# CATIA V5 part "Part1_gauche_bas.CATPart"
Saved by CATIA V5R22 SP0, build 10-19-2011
Part number: Part1
Bounding box of the stored display mesh (mm): x -87.5 to 0, y -87.5 to 89.999, z 0 to 150
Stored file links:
  C:\Users\dussa\Documents\ENIB\S5\inter\Part1_gauche_bas.CATPart
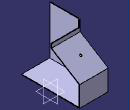
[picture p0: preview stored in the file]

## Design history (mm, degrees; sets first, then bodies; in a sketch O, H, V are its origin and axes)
Body1 (main body)
  Sketch1 on xy-plane, origin (0, 0, 0), H (1, 0, 0), V (0, 1, 0)
    line L1 (-87.5, 87.5) -> (87.5, 87.5)
    line L2 (87.5, 87.5) -> (87.5, -87.5)
    line L3 (87.5, -87.5) -> (-87.5, -87.5)
    line L4 (-87.5, -87.5) -> (-87.5, 87.5)
    distance L1 L3 = 175
    distance L4 L2 = 175
    horizontal: L1 H, L3 H
    vertical: L2 V, L4 V
    symmetry: L3 L1 H, L4 L2 V
  Pad1: profile Sketch1, direction (0, 0, 1), length 2
  Sketch2 on face of Pad1 from Sketch1.L2, origin (87.5, 0, 0), H (0, 1, 0), V (0, 0, 1)
    point P1 (-87.5, 0)
    line L1 (-87.5, 0) -> (87.5, 0)
    line L2 (87.5, 0) -> (87.5, 62.3217)
    line L3 (-87.5, 80) -> (-87.5, 0)
    point P3 (87.5, 62.3217)
    point P4 (-87.5, 80)
    reference projected line E1 (-87.5, 0) -> (-87.5, 2) from edge [face of Pad1 from Sketch1.L2 | face of Pad1 from Sketch1.L3]
    reference projected line E2 (87.5, 0) -> (87.5, 2) from edge [face of Pad1 from Sketch1.L1 | face of Pad1 from Sketch1.L2]
    reference projected line E3 (-87.5, 0) -> (87.5, 0) from edge [start face of Pad1 | face of Pad1 from Sketch1.L2]
    line L4 (-87.5, 300) -> (2.5, 300)
    line L5 (2.5, 300) -> (2.5, 115)
    line L6 (-87.5, 80) -> (-87.5, 300)
    point P8 (-87.5, 80)
    line L7 (2.5, 115) -> (87.5, 62.3217)
    point P9 (87.5, 62.3217)
    distance P4 P1 = 80
    distance L1 L4 = 300
    length L5 = 185
    distance L5 L6 = 90
    length L7 = 100
    horizontal: L1 H, L4 H
    vertical: L2 V, L3 V, L5 V, L6 V
    coincidence: E1 L3, L2 E2, L1 E3, L6 L3, P8 P4, L7 P3, P3 P9
  Pad2: profile Sketch2, direction (1, 0, 0), length 2
  Sketch3 on face of Pad1 from Sketch1.L4, origin (-87.5, 0, 0), H (0, 1, 0), V (0, 0, 1)
    point P1 (-87.5, 0)
    line L1 (-87.5, 0) -> (87.5, 0)
    line L2 (87.5, 0) -> (87.5, 62.3217)
    line L3 (-87.5, 80) -> (-87.5, 0)
    point P3 (87.5, 62.3217)
    point P4 (-87.5, 80)
    reference projected line E1 (-87.5, 0) -> (-87.5, 2) from edge [face of Pad1 from Sketch1.L2 | face of Pad1 from Sketch1.L3]
    reference projected line E2 (87.5, 0) -> (87.5, 2) from edge [face of Pad1 from Sketch1.L1 | face of Pad1 from Sketch1.L2]
    reference projected line E3 (-87.5, 0) -> (87.5, 0) from edge [start face of Pad1 | face of Pad1 from Sketch1.L2]
    line L4 (-87.5, 300) -> (2.5, 300)
    line L5 (2.5, 300) -> (2.5, 115)
    line L6 (-87.5, 80) -> (-87.5, 300)
    point P8 (-87.5, 80)
    line L7 (2.5, 115) -> (87.5, 62.3217)
    point P9 (87.5, 62.3217)
    distance P4 P1 = 80
    distance L1 L4 = 300
    length L5 = 185
    distance L5 L6 = 90
    length L7 = 100
    horizontal: L1 H, L4 H
    vertical: L2 V, L3 V, L5 V, L6 V
    coincidence: E1 L3, L2 E2, L1 E3, L6 L3, P8 P4, L7 P3, P3 P9
  Pad3: profile Sketch3, direction (1, 0, 0), length 2
  Sketch4 on face of Pad3 from Sketch3.L4, origin (0, 0, 300), H (1, 0, 0), V (0, 1, 0)
    line L1 (-87.5, 2.5) -> (89.5, 2.5)
    line L2 (89.5, 2.5) -> (89.5, -87.5)
    line L3 (89.5, -87.5) -> (-87.5, -87.5)
    line L4 (-87.5, -87.5) -> (-87.5, 2.5)
    reference projected line E1 (-87.5, -87.5) -> (87.5, -87.5) from edge [face of Pad3 | end face of Pad1]
    reference projected point E2 (89.5, 2.5) from vertex [face of Pad2 from Sketch2.L5 | face of Pad2 from Sketch2.L4 | end face of Pad2]
    reference projected line E3 (-87.5, 2.5) -> (-87.5, -87.5) from edge [start face of Pad3 | face of Pad3 from Sketch3.L4]
    reference projected line E4 (89.5, 2.5) -> (89.5, -87.5) from edge [face of Pad2 from Sketch2.L4 | end face of Pad2]
    horizontal: L1 H, L3 H
    vertical: L2 V, L4 V
    coincidence: L3 E1, L1 E2, L4 E3, E4 L2
  Pad4: profile Sketch4, direction (0, 0, 1), length 2
  Sketch5 on face of Pad3, origin (0, 87.5, 0), H (-1, 0, 0), V (0, 0, 1)
    line L1 (-89.5, 62.3217) -> (87.5, 62.3217)
    line L2 (87.5, 62.3217) -> (87.5, 0)
    line L3 (87.5, 0) -> (-89.5, 0)
    line L4 (-89.5, 0) -> (-89.5, 62.3217)
    reference projected point E1 (85.5, 62.3217) from vertex [end face of Pad3 | face of Pad3 from Sketch3.L2 | face of Pad3 from Sketch3.L7]
    reference projected line E2 (-87.5, 0) -> (87.5, 0) from edge [face of Pad3 | face of Pad3]
    reference projected line E3 (87.5, 0) -> (87.5, 2) from edge [face of Pad3 | face of Pad3]
    reference projected line E4 (-89.5, 0) -> (-89.5, 62.3217) from edge [face of Pad3 | end face of Pad2]
    horizontal: L1 H, L3 H
    vertical: L2 V, L4 V
    coincidence: E1 L1, E2 L3, L2 E3, E4 L4
  Pad5: profile Sketch5, direction (0, 1, 0), length 2
  Sketch6 on face of Pad2 from Sketch2.L7, origin (0, 52.1868, 84.2069), H (-1, 0, 0), V (0, -0.85, 0.5268)
    line L1 (-89.5, 58.455) -> (87.5, 58.455)
    line L2 (87.5, 58.455) -> (87.5, -43.245)
    line L3 (87.5, -43.245) -> (-89.5, -43.245)
    line L4 (-89.5, -43.245) -> (-89.5, 58.455)
    reference projected line E1 (87.5, -43.245) -> (-89.5, -43.245) from edge [face of Pad5 from Sketch5.L1 | end face of Pad5]
    reference projected line E2 (87.5, -41.545) -> (87.5, 58.455) from edge [face of Pad5 | face of Pad3 from Sketch3.L7]
    reference projected line E3 (87.5, 58.455) -> (85.5, 58.455) from edge [face of Pad3 from Sketch3.L5 | face of Pad3 from Sketch3.L7]
    reference projected line E4 (-89.5, -41.545) -> (-89.5, 58.455) from edge [face of Pad2 from Sketch2.L7 | face of Pad5]
    circle A1 centre (-50, 11.755) radius 14.5
    point P5 (-50, 11.755)
    circle A2 centre (50, 11.755) radius 3.35
    point P6 (50, 11.755)
    radius A1 = 14.5
    radius A2 = 3.35
    distance P5 V = 50
    distance P6 V = 50
    distance P5 L3 = 55
    distance P6 L3 = 55
    horizontal: L1 H, L3 H
    vertical: L2 V, L4 V
    coincidence: L3 E1, L2 E2, E3 L1, L4 E4
  Pad6: profile Sketch6, direction (0, 0.5268, 0.85), length 2
  Sketch7 on face of Pad3 from Sketch3.L5, origin (0, 2.5, 0), H (-1, 0, 0), V (0, 0, 1)
    line L1 (-89.5, 302) -> (87.5, 302)
    line L2 (87.5, 302) -> (87.5, 116.7)
    line L3 (87.5, 116.7) -> (-89.5, 116.7)
    line L4 (-89.5, 116.7) -> (-89.5, 302)
    reference projected line E1 (-89.5, 302) -> (87.5, 302) from edge [face of Pad4 from Sketch4.L1 | end face of Pad4]
    reference projected line E2 (87.5, 116.7) -> (-89.5, 116.7) from edge [face of Pad6 from Sketch6.L1 | end face of Pad6]
    reference projected line E3 (-89.5, 115) -> (-89.5, 300) from edge [face of Pad2 from Sketch2.L5 | face of Pad6]
    reference projected line E4 (87.5, 115) -> (87.5, 300) from edge [face of Pad6 | face of Pad3 from Sketch3.L5]
    line L5 (-86, 298.5) -> (84, 298.5)
    line L6 (84, 298.5) -> (84, 128.5)
    line L7 (84, 128.5) -> (-86, 128.5)
    line L8 (-86, 128.5) -> (-86, 298.5)
    distance L6 L8 = 170
    distance L5 L7 = 170
    distance L5 L1 = 3.5
    distance L8 L4 = 3.5
    horizontal: L1 H, L3 H, L5 H, L7 H
    vertical: L2 V, L4 V, L6 V, L8 V
    coincidence: L1 E1, L3 E2, L4 E3, L2 E4
  Pad7: profile Sketch7, direction (0, 1, 0), length 2
  Split1: SplitPlane {plane type Offset, RefPlane yz-plane, Offset 0}
  Split2: SplitPlane {plane type Offset, Offset 150, RefPlane xy-plane}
